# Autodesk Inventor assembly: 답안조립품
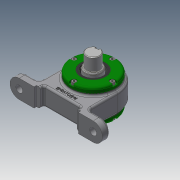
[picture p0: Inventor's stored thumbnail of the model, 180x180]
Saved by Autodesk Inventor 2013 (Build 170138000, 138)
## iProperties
Created: 2019-05
Part Number: 답안조립품
Document SubType Name: Assembly
Designer: user
Author: user
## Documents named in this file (13)
- C:\Users\user\Desktop\490504V1011\답안조립품.iam
- C:\Users\user\Desktop\490504V1011\본체.ipt
- C:\Users\user\Desktop\490504V1011\개스킷.ipt
- C:\Users\user\Desktop\490504V1011\그리스니플 M6.ipt
- 그리스니플  M6.ipt
- C:\Users\user\Desktop\490504V1011\그리스니플개스킷.ipt
- C:\Users\user\Desktop\490504V1011\베어링너트.ipt
- C:\Users\user\Desktop\490504V1011\볼트 M4.ipt
- C:\Users\user\Desktop\490504V1011\앵귤러 볼 베어링 7205.ipt
- C:\Users\user\Desktop\490504V1011\오일 실 28 40 5 B.ipt
- C:\Users\user\Desktop\490504V1011\축.ipt
- C:\Users\user\Desktop\490504V1011\칼라.ipt
- C:\Users\user\Desktop\490504V1011\커버.ipt
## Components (4 placed, 3 different names)
1. 개스킷:1
2. 그리스니플  M6:1
3. 그리스니플개스킷:1
4. 개스킷:2
